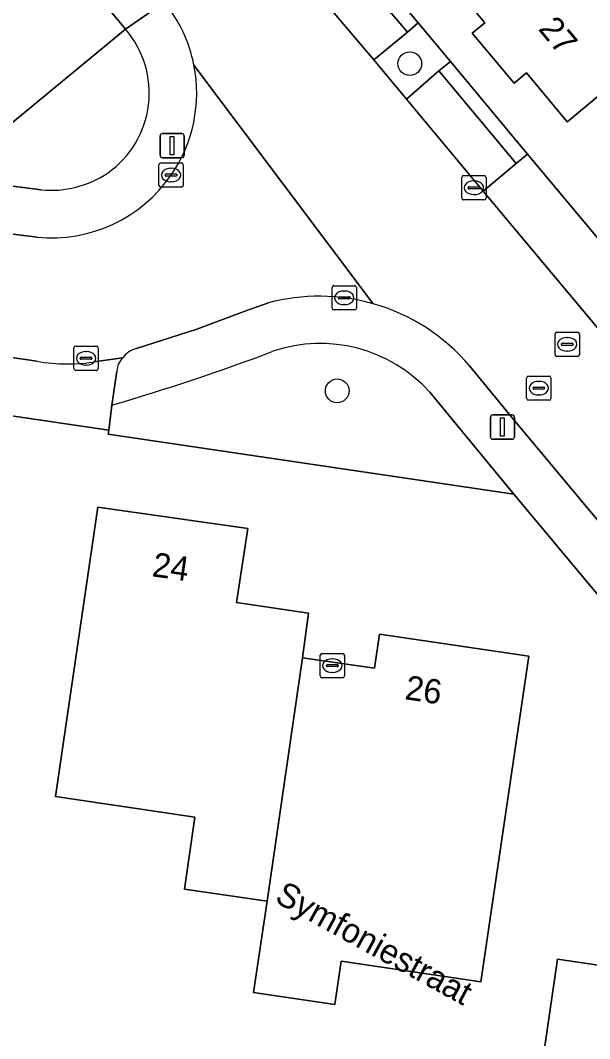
# Model space of a CAD drawing. Extents: x 164148 to 165261, y 382513 to 383432.
# Drawn here: x 164753.29 to 164776.74, y 383011.96 to 383053.88 of the extents above; entities that cross this region are included whole.
import ezdxf

# ---------------------------------------------------------------- set-up
doc = ezdxf.new("R2010")
doc.units = 0
for name, color, linetype in [('IMGEO_Boom', 7, 'Continuous'), ('IMGEO_Erf', 7, 'Continuous'), ('IMGEO_Groenvoorziening', 7, 'Continuous'), ('IMGEO_Kolk', 7, 'Continuous'), ('IMGEO_Lichtmast', 7, 'Continuous'), ('IMGEO_Openbare_ruimte_label', 7, 'Continuous'), ('IMGEO_Pand', 7, 'Continuous'), ('IMGEO_Pand_nummerreeks', 7, 'Continuous'), ('IMGEO_Parkeervlak_open', 7, 'Continuous'), ('IMGEO_Rijbaan_lokaal_open', 7, 'Continuous'), ('IMGEO_Rioolput', 7, 'Continuous'), ('IMGEO_Voetpad_open', 7, 'Continuous')]:
    doc.layers.add(name, color=color, linetype=linetype)

msp = doc.modelspace()

# ---------------------------------------------------------------- linework, layer by layer
at = {"layer": 'IMGEO_Boom'}
for centre in [(164769.334, 383052.103), (164766.345, 383038.63)]:
    msp.add_circle(centre, 0.489, dxfattribs=at)
at = {"layer": 'IMGEO_Erf'}
for points in [[(164685.42, 383135.126), (164682.705, 383117.517), (164682.279, 383114.453), (164685.334, 383113.998), (164688.257, 383113.615), (164687.868, 383110.687), (164684.941, 383111.045), (164681.864, 383111.47), (164680.372, 383101.254), (164679.477, 383095.307), (164679.334, 383094.335), (164679.22, 383092.548), (164677.944, 383082.474), (164677.674, 383082.494), (164677.503, 383081.521), (164676.599, 383075.668), (164674.064, 383058.631), (164743.462, 383048.39), (164750.216, 383047.411), (164757.629, 383053.516), (164711.831, 383108.452)], [(164766.59, 383057.489), (164769.673, 383053.79), (164771.005, 383052.196), (164774.189, 383048.376), (164779.454, 383042.072), (164782.539, 383038.402), (164783.857, 383036.783), (164787.032, 383033.002), (164792.262, 383026.731), (164795.373, 383023.024), (164796.68, 383021.442)]]:
    msp.add_lwpolyline(points, dxfattribs=at)
for points in [[(164774.713, 383068.268), (164780.486, 383061.369), (164786.258, 383054.47), (164781.652, 383050.629), (164779.717, 383052.949), (164775.871, 383049.742), (164775.823, 383049.702), (164774.139, 383051.722), (164773.628, 383051.296), (164771.905, 383053.356), (164772.419, 383053.785), (164772.009, 383054.277), (164768.168, 383058.885), (164772.051, 383062.122), (164770.12, 383064.439)], [(164773.625, 383034.37), (164756.914, 383036.848), (164756.945, 383037.007), (164750.961, 383037.884), (164745.467, 383038.7), (164743.325, 383039.011), (164732.535, 383040.594), (164726.832, 383041.442), (164721.322, 383042.249), (164719.176, 383042.567), (164708.591, 383044.131), (164702.568, 383045.027), (164697.666, 383045.734), (164696.644, 383045.892), (164694.5, 383046.223), (164676.627, 383048.817), (164672.72, 383049.384), (164670.369, 383036.742), (164669.457, 383030.808), (164668.043, 383018.43), (164792.926, 382999.883), (164794.329, 383009.577), (164793.988, 383009.985)], [(164764.912, 383027.637), (164767.886, 383027.211), (164768.092, 383028.613), (164774.238, 383027.703), (164772.256, 383014.304), (164766.51, 383015.154), (164766.246, 383013.368), (164762.899, 383013.863), (164763.455, 383017.62), (164760.052, 383018.118), (164760.487, 383021.077), (164754.735, 383021.923), (164756.488, 383033.841), (164762.657, 383032.956), (164762.202, 383029.922), (164765.166, 383029.471)], [(164784.293, 383018.222), (164784.196, 383017.562), (164785.081, 383017.432), (164783.318, 383005.501), (164774.198, 383006.849), (164775.415, 383015.23), (164778.393, 383014.789), (164778.918, 383018.342), (164781.485, 383017.963), (164781.583, 383018.623)]]:
    msp.add_lwpolyline(points, close=True, dxfattribs=at)
at = {"layer": 'IMGEO_Groenvoorziening'}
msp.add_lwpolyline([(164769.673, 383053.79), (164769.236, 383053.402), (164767.857, 383052.253), (164769.192, 383050.647), (164770.53, 383051.801), (164771.005, 383052.196)], close=True, dxfattribs=at)
for points in [[(164757.629, 383053.516), (164750.216, 383047.411), (164754.15, 383046.907)], [(164757.064, 383038.043), (164756.945, 383037.007), (164756.914, 383036.848), (164773.625, 383034.37), (164770.154, 383038.576)]]:
    msp.add_lwpolyline(points, dxfattribs=at)
for centre, radius, start, end in [((164754.581, 383050.892), 4.022, 305.3329, 40.7253), ((164754.557, 383051.062), 4.175, 264.3994, 304.2494), ((164731.985, 383124.094), 89.631, 286.24859, 290.71977), ((164765.647, 383034.515), 6.067, 42.0159, 108.7539)]:
    msp.add_arc(centre, radius, start, end, dxfattribs=at)
at = {"layer": 'IMGEO_Kolk'}
for p, q in [((164759.004, 383047.091), (164759.004, 383047.943)), ((164759.079, 383048.017), (164759.931, 383048.017)), ((164760.005, 383047.943), (164760.005, 383047.091)), ((164759.263, 383047.511), (164759.263, 383047.523)), ((164759.701, 383047.474), (164759.303, 383047.474)), ((164759.306, 383047.56), (164759.704, 383047.56)), ((164759.492, 383047.797), (164759.517, 383047.797)), ((164759.747, 383047.523), (164759.747, 383047.511)), ((164771.474, 383046.566), (164771.474, 383047.418)), ((164771.549, 383047.492), (164772.401, 383047.492)), ((164772.475, 383047.418), (164772.475, 383046.566)), ((164759.931, 383047.017), (164759.079, 383047.017)), ((164759.515, 383047.237), (164759.49, 383047.237)), ((164771.733, 383046.986), (164771.733, 383046.998)), ((164771.776, 383047.035), (164772.174, 383047.035)), ((164771.962, 383047.272), (164771.987, 383047.272)), ((164772.217, 383046.998), (164772.217, 383046.986)), ((164772.171, 383046.949), (164771.773, 383046.949)), ((164771.985, 383046.712), (164771.96, 383046.712)), ((164772.401, 383046.492), (164771.549, 383046.492)), ((164766.133, 383042.035), (164766.133, 383042.887)), ((164766.208, 383042.961), (164767.06, 383042.961)), ((164767.134, 383042.887), (164767.134, 383042.035)), ((164766.392, 383042.455), (164766.392, 383042.467)), ((164766.83, 383042.418), (164766.432, 383042.418)), ((164766.435, 383042.504), (164766.833, 383042.504)), ((164766.621, 383042.741), (164766.646, 383042.741)), ((164766.876, 383042.467), (164766.876, 383042.455)), ((164767.06, 383041.961), (164766.208, 383041.961)), ((164766.644, 383042.181), (164766.619, 383042.181)), ((164755.501, 383039.547), (164755.501, 383040.399)), ((164755.576, 383040.473), (164756.428, 383040.473)), ((164756.502, 383040.399), (164756.502, 383039.547)), ((164755.76, 383039.967), (164755.76, 383039.979)), ((164756.198, 383039.93), (164755.8, 383039.93)), ((164755.803, 383040.016), (164756.201, 383040.016)), ((164755.989, 383040.253), (164756.014, 383040.253)), ((164756.244, 383039.979), (164756.244, 383039.967)), ((164756.428, 383039.473), (164755.576, 383039.473)), ((164756.012, 383039.693), (164755.987, 383039.693))]:
    msp.add_line(p, q, dxfattribs=at)
for points in [[(164759.004, 383047.091), (164759.004, 383047.943)], [(164759.079, 383048.017), (164759.931, 383048.017)], [(164760.005, 383047.943), (164760.005, 383047.091)], [(164771.474, 383046.566), (164771.474, 383047.418)], [(164771.549, 383047.492), (164772.401, 383047.492)], [(164772.475, 383047.418), (164772.475, 383046.566)], [(164759.931, 383047.017), (164759.079, 383047.017)], [(164772.401, 383046.492), (164771.549, 383046.492)], [(164766.133, 383042.035), (164766.133, 383042.887)], [(164766.208, 383042.961), (164767.06, 383042.961)], [(164767.134, 383042.887), (164767.134, 383042.035)], [(164767.06, 383041.961), (164766.208, 383041.961)], [(164755.501, 383039.547), (164755.501, 383040.399)], [(164755.576, 383040.473), (164756.428, 383040.473)], [(164756.502, 383040.399), (164756.502, 383039.547)], [(164756.428, 383039.473), (164755.576, 383039.473)]]:
    msp.add_lwpolyline(points, dxfattribs=at)
for centre, radius, start, end in [((164759.081, 383047.941), 0.0765, 91.552, 178.448), ((164759.081, 383047.941), 0.0765, 91.552, 178.448), ((164759.929, 383047.941), 0.0765, 1.552, 88.448), ((164759.929, 383047.941), 0.0765, 1.552, 88.448), ((164759.303, 383047.52), 0.0403, 85.8775, 175.7526), ((164759.3, 383047.51), 0.0366, 178.938, 274.7102), ((164759.704, 383047.517), 0.043, 264.8664, 352.4533), ((164759.708, 383047.522), 0.0386, 1.7309, 96.639), ((164771.551, 383047.416), 0.0765, 91.552, 178.448), ((164771.551, 383047.416), 0.0765, 91.552, 178.448), ((164772.399, 383047.416), 0.0765, 1.552, 88.448), ((164772.399, 383047.416), 0.0765, 1.552, 88.448), ((164759.081, 383047.093), 0.0765, 181.552, 268.448), ((164759.081, 383047.093), 0.0765, 181.552, 268.448), ((164759.929, 383047.093), 0.0765, 271.552, 358.448), ((164759.929, 383047.093), 0.0765, 271.552, 358.448), ((164771.773, 383046.995), 0.0403, 85.8775, 175.7526), ((164771.77, 383046.985), 0.0366, 178.938, 274.7102), ((164772.174, 383046.992), 0.043, 264.8664, 352.4533), ((164772.178, 383046.997), 0.0386, 1.7309, 96.639), ((164771.551, 383046.568), 0.0765, 181.552, 268.448), ((164771.551, 383046.568), 0.0765, 181.552, 268.448), ((164772.399, 383046.568), 0.0765, 271.552, 358.448), ((164772.399, 383046.568), 0.0765, 271.552, 358.448), ((164766.21, 383042.885), 0.0765, 91.552, 178.448), ((164766.21, 383042.885), 0.0765, 91.552, 178.448), ((164767.058, 383042.885), 0.0765, 1.552, 88.448), ((164767.058, 383042.885), 0.0765, 1.552, 88.448), ((164766.432, 383042.464), 0.0403, 85.8775, 175.7526), ((164766.429, 383042.454), 0.0366, 178.938, 274.7102), ((164766.833, 383042.461), 0.043, 264.8664, 352.4533), ((164766.837, 383042.466), 0.0386, 1.7309, 96.639), ((164766.21, 383042.037), 0.0765, 181.552, 268.448), ((164766.21, 383042.037), 0.0765, 181.552, 268.448), ((164767.058, 383042.037), 0.0765, 271.552, 358.448), ((164767.058, 383042.037), 0.0765, 271.552, 358.448), ((164755.578, 383040.397), 0.0765, 91.552, 178.448), ((164755.578, 383040.397), 0.0765, 91.552, 178.448), ((164756.426, 383040.397), 0.0765, 1.552, 88.448), ((164756.426, 383040.397), 0.0765, 1.552, 88.448), ((164755.8, 383039.976), 0.0403, 85.8775, 175.7526), ((164755.797, 383039.966), 0.0366, 178.938, 274.7102), ((164756.201, 383039.973), 0.043, 264.8664, 352.4533), ((164756.205, 383039.978), 0.0386, 1.7309, 96.639), ((164755.578, 383039.549), 0.0765, 181.552, 268.448), ((164755.578, 383039.549), 0.0765, 181.552, 268.448), ((164756.426, 383039.549), 0.0765, 271.552, 358.448), ((164756.426, 383039.549), 0.0765, 271.552, 358.448)]:
    msp.add_arc(centre, radius, start, end, dxfattribs=at)
for centre, major_axis, ratio, start_param, end_param in [((164759.491, 383047.517), (-0.387, 0.002), 0.722429, 4.712389, 7.853982), ((164759.516, 383047.517), (-0.39, 0.002), 0.717154, 1.570796, 4.712389), ((164771.961, 383046.992), (-0.387, 0.002), 0.722429, 4.712389, 7.853982), ((164771.986, 383046.992), (-0.39, 0.002), 0.717154, 1.570796, 4.712389), ((164766.62, 383042.461), (-0.387, 0.002), 0.722429, 4.712389, 7.853982), ((164766.645, 383042.461), (-0.39, 0.002), 0.717154, 1.570796, 4.712389), ((164755.988, 383039.973), (-0.387, 0.002), 0.722429, 4.712389, 7.853982), ((164756.013, 383039.973), (-0.39, 0.002), 0.717154, 1.570796, 4.712389)]:
    msp.add_ellipse(centre, major_axis=major_axis, ratio=ratio, start_param=start_param, end_param=end_param, dxfattribs=at)
at = {"layer": 'IMGEO_Lichtmast'}
for p, q in [((164759.05, 383048.327), (164759.05, 383049.127)), ((164759.05, 383049.127), (164759.05, 383048.327)), ((164759.15, 383049.227), (164759.94, 383049.227)), ((164759.94, 383049.227), (164759.15, 383049.227)), ((164760.04, 383049.127), (164760.04, 383048.327)), ((164760.04, 383048.327), (164760.04, 383049.127)), ((164759.94, 383048.227), (164759.15, 383048.227)), ((164759.15, 383048.227), (164759.94, 383048.227)), ((164772.657, 383036.738), (164772.657, 383037.538)), ((164772.657, 383037.538), (164772.657, 383036.738)), ((164772.757, 383037.638), (164773.547, 383037.638)), ((164773.547, 383037.638), (164772.757, 383037.638)), ((164773.647, 383037.538), (164773.647, 383036.738)), ((164773.647, 383036.738), (164773.647, 383037.538)), ((164773.547, 383036.638), (164772.757, 383036.638)), ((164772.757, 383036.638), (164773.547, 383036.638))]:
    msp.add_line(p, q, dxfattribs=at)
for points in [[(164759.47, 383049.102), (164759.62, 383049.102), (164759.62, 383048.352), (164759.47, 383048.352), (164759.47, 383049.102)], [(164773.077, 383037.513), (164773.227, 383037.513), (164773.227, 383036.763), (164773.077, 383036.763), (164773.077, 383037.513)]]:
    msp.add_lwpolyline(points, dxfattribs=at)
for centre, start, end in [((164759.15, 383049.127), 90, 180), ((164759.15, 383049.127), 90, 180), ((164759.94, 383049.127), 0, 90), ((164759.94, 383049.127), 360, 90), ((164759.15, 383048.327), 180, 270), ((164759.15, 383048.327), 180, 270), ((164759.94, 383048.327), 270, 0), ((164759.94, 383048.327), 270, 0), ((164772.757, 383037.538), 90, 180), ((164772.757, 383037.538), 90, 180), ((164773.547, 383037.538), 0, 90), ((164773.547, 383037.538), 360, 90), ((164772.757, 383036.738), 180, 270), ((164772.757, 383036.738), 180, 270), ((164773.547, 383036.738), 270, 0), ((164773.547, 383036.738), 270, 0)]:
    msp.add_arc(centre, 0.1, start, end, dxfattribs=at)
at = {"layer": 'IMGEO_Pand'}
for points in [[(164780.486, 383061.369), (164772.009, 383054.277), (164772.419, 383053.785), (164771.905, 383053.356), (164773.628, 383051.296), (164774.139, 383051.722), (164775.823, 383049.702), (164775.871, 383049.742), (164779.717, 383052.949), (164781.652, 383050.629), (164786.258, 383054.47)], [(164764.912, 383027.637), (164765.166, 383029.471), (164762.202, 383029.922), (164762.657, 383032.956), (164756.488, 383033.841), (164754.735, 383021.923), (164760.487, 383021.077), (164760.052, 383018.118), (164763.455, 383017.62)], [(164768.092, 383028.613), (164767.886, 383027.211), (164764.912, 383027.637), (164763.455, 383017.62), (164762.899, 383013.863), (164766.246, 383013.368), (164766.51, 383015.154), (164772.256, 383014.304), (164774.238, 383027.703)], [(164785.081, 383017.432), (164784.196, 383017.562), (164784.293, 383018.222), (164781.583, 383018.623), (164781.485, 383017.963), (164778.918, 383018.342), (164778.393, 383014.789), (164775.415, 383015.23), (164774.198, 383006.849), (164783.318, 383005.501)]]:
    msp.add_lwpolyline(points, close=True, dxfattribs=at)
at = {"layer": 'IMGEO_Parkeervlak_open'}
for points in [[(164766.111, 383057.083), (164764.743, 383055.943), (164767.857, 383052.253), (164769.236, 383053.402)], [(164770.53, 383051.801), (164769.192, 383050.647), (164772.36, 383046.857), (164773.722, 383047.994)]]:
    msp.add_lwpolyline(points, close=True, dxfattribs=at)
at = {"layer": 'IMGEO_Rijbaan_lokaal_open'}
for points in [[(164814.316, 382986.078), (164824.191, 382984.713), (164822.339, 382987.011), (164822.315, 382987.027), (164817.568, 382992.747), (164814.483, 382996.412), (164810.702, 383000.916), (164807.691, 383004.534), (164806.408, 383006.093), (164803.165, 383009.943), (164798.018, 383016.107), (164794.843, 383019.914), (164793.463, 383021.56), (164790.41, 383025.204), (164785.193, 383031.48), (164782.046, 383035.254), (164780.707, 383036.845), (164777.624, 383040.546), (164772.36, 383046.857), (164769.192, 383050.647), (164767.857, 383052.253), (164764.743, 383055.943), (164759.595, 383062.145)], [(164767.829, 383042.216), (164760.445, 383052.045)], [(164760.445, 383052.045), (164767.829, 383042.216)], [(164676.537, 383051.56), (164678.434, 383050.981), (164694.856, 383048.566), (164696.992, 383048.254), (164702.925, 383047.374), (164708.937, 383046.498), (164719.525, 383044.915), (164721.668, 383044.591), (164727.191, 383043.797), (164732.888, 383042.965), (164743.671, 383041.354), (164745.824, 383041.051), (164751.336, 383040.234), (164753.976, 383039.849)], [(164753.985, 383044.958), (164749.891, 383045.466), (164743.727, 383046.37), (164723.716, 383049.326)], [(164758.078, 383040.379), (164760.568, 383041.168), (164762.583, 383041.927), (164763.51, 383042.252)], [(164756.435, 383039.836), (164757.508, 383039.995)], [(164771.8, 383039.66), (164773.622, 383037.443), (164782.029, 383027.366), (164793.721, 383013.372), (164807.417, 382996.914), (164810.146, 382993.692), (164812.326, 382991.078)]]:
    msp.add_lwpolyline(points, dxfattribs=at)
for centre, radius, start, end in [((164754.627, 383050.887), 5.932, 11.2559, 39.1698), ((164754.626, 383050.891), 5.932, 325.3304, 11.2138), ((164754.578, 383050.911), 5.983, 264.3074, 325.4363), ((164765.604, 383034.401), 8.125, 74.1087, 104.9362), ((164765.606, 383034.4), 8.126, 40.3397, 74.1242), ((164758.328, 383039.393), 1.017, 104.2286, 143.7065), ((164755.243, 383046.997), 7.259, 259.946, 279.4482)]:
    msp.add_arc(centre, radius, start, end, dxfattribs=at)
at = {"layer": 'IMGEO_Rioolput'}
for p, q in [((164775.317, 383040.12), (164775.317, 383040.972)), ((164775.392, 383041.046), (164776.244, 383041.046)), ((164775.805, 383040.826), (164775.83, 383040.826)), ((164776.318, 383040.972), (164776.318, 383040.12)), ((164775.576, 383040.54), (164775.576, 383040.552)), ((164776.014, 383040.503), (164775.616, 383040.503)), ((164775.619, 383040.589), (164776.017, 383040.589)), ((164775.828, 383040.266), (164775.803, 383040.266)), ((164776.06, 383040.552), (164776.06, 383040.54)), ((164776.244, 383040.046), (164775.392, 383040.046)), ((164774.148, 383038.315), (164774.148, 383039.167)), ((164774.223, 383039.241), (164775.075, 383039.241)), ((164774.636, 383039.021), (164774.661, 383039.021)), ((164775.149, 383039.167), (164775.149, 383038.315)), ((164774.407, 383038.735), (164774.407, 383038.747)), ((164774.845, 383038.698), (164774.447, 383038.698)), ((164774.45, 383038.784), (164774.848, 383038.784)), ((164774.891, 383038.747), (164774.891, 383038.735)), ((164775.075, 383038.241), (164774.223, 383038.241)), ((164774.659, 383038.461), (164774.634, 383038.461)), ((164765.643, 383026.891), (164765.643, 383027.743)), ((164765.718, 383027.817), (164766.57, 383027.817)), ((164766.644, 383027.743), (164766.644, 383026.891)), ((164765.902, 383027.311), (164765.902, 383027.323)), ((164766.34, 383027.274), (164765.942, 383027.274)), ((164765.945, 383027.36), (164766.343, 383027.36)), ((164766.131, 383027.597), (164766.156, 383027.597)), ((164766.386, 383027.323), (164766.386, 383027.311)), ((164766.154, 383027.037), (164766.129, 383027.037)), ((164766.57, 383026.817), (164765.718, 383026.817))]:
    msp.add_line(p, q, dxfattribs=at)
for points in [[(164775.317, 383040.12), (164775.317, 383040.972)], [(164775.392, 383041.046), (164776.244, 383041.046)], [(164776.318, 383040.972), (164776.318, 383040.12)], [(164776.244, 383040.046), (164775.392, 383040.046)], [(164774.148, 383038.315), (164774.148, 383039.167)], [(164774.223, 383039.241), (164775.075, 383039.241)], [(164775.149, 383039.167), (164775.149, 383038.315)], [(164775.075, 383038.241), (164774.223, 383038.241)], [(164765.643, 383026.891), (164765.643, 383027.743)], [(164765.718, 383027.817), (164766.57, 383027.817)], [(164766.644, 383027.743), (164766.644, 383026.891)], [(164766.57, 383026.817), (164765.718, 383026.817)]]:
    msp.add_lwpolyline(points, dxfattribs=at)
for centre, radius, start, end in [((164775.394, 383040.97), 0.0765, 91.552, 178.448), ((164775.394, 383040.97), 0.0765, 91.552, 178.448), ((164776.242, 383040.97), 0.0765, 1.552, 88.448), ((164776.242, 383040.97), 0.0765, 1.552, 88.448), ((164775.616, 383040.549), 0.0403, 85.8775, 175.7526), ((164775.613, 383040.539), 0.0366, 178.938, 274.7102), ((164776.017, 383040.546), 0.043, 264.8664, 352.4533), ((164776.021, 383040.551), 0.0386, 1.7309, 96.639), ((164775.394, 383040.122), 0.0765, 181.552, 268.448), ((164775.394, 383040.122), 0.0765, 181.552, 268.448), ((164776.242, 383040.122), 0.0765, 271.552, 358.448), ((164776.242, 383040.122), 0.0765, 271.552, 358.448), ((164774.225, 383039.165), 0.0765, 91.552, 178.448), ((164774.225, 383039.165), 0.0765, 91.552, 178.448), ((164775.073, 383039.165), 0.0765, 1.552, 88.448), ((164775.073, 383039.165), 0.0765, 1.552, 88.448), ((164774.447, 383038.744), 0.0403, 85.8775, 175.7526), ((164774.444, 383038.734), 0.0366, 178.938, 274.7102), ((164774.848, 383038.741), 0.043, 264.8664, 352.4533), ((164774.852, 383038.746), 0.0386, 1.7309, 96.639), ((164774.225, 383038.317), 0.0765, 181.552, 268.448), ((164774.225, 383038.317), 0.0765, 181.552, 268.448), ((164775.073, 383038.317), 0.0765, 271.552, 358.448), ((164775.073, 383038.317), 0.0765, 271.552, 358.448), ((164765.72, 383027.741), 0.0765, 91.552, 178.448), ((164765.72, 383027.741), 0.0765, 91.552, 178.448), ((164766.568, 383027.741), 0.0765, 1.552, 88.448), ((164766.568, 383027.741), 0.0765, 1.552, 88.448), ((164765.942, 383027.32), 0.0403, 85.8775, 175.7526), ((164765.939, 383027.31), 0.0366, 178.938, 274.7102), ((164766.343, 383027.317), 0.043, 264.8664, 352.4533), ((164766.347, 383027.322), 0.0386, 1.7309, 96.639), ((164765.72, 383026.893), 0.0765, 181.552, 268.448), ((164765.72, 383026.893), 0.0765, 181.552, 268.448), ((164766.568, 383026.893), 0.0765, 271.552, 358.448), ((164766.568, 383026.893), 0.0765, 271.552, 358.448)]:
    msp.add_arc(centre, radius, start, end, dxfattribs=at)
for centre, major_axis, ratio, start_param, end_param in [((164775.804, 383040.546), (-0.387, 0.002), 0.722429, 4.712389, 7.853982), ((164775.829, 383040.546), (-0.39, 0.002), 0.717154, 1.570796, 4.712389), ((164774.635, 383038.741), (-0.387, 0.002), 0.722429, 4.712389, 7.853982), ((164774.66, 383038.741), (-0.39, 0.002), 0.717154, 1.570796, 4.712389), ((164766.13, 383027.317), (-0.387, 0.002), 0.722429, 4.712389, 7.853982), ((164766.155, 383027.317), (-0.39, 0.002), 0.717154, 1.570796, 4.712389)]:
    msp.add_ellipse(centre, major_axis=major_axis, ratio=ratio, start_param=start_param, end_param=end_param, dxfattribs=at)
at = {"layer": 'IMGEO_Voetpad_open'}
for points in [[(164693.959, 383129.801), (164704.347, 383117.418), (164711.831, 383108.452), (164757.629, 383053.516), (164759.226, 383054.634), (164755.138, 383059.563), (164742.049, 383075.319), (164733.429, 383085.658)], [(164754.15, 383046.907), (164750.216, 383047.411), (164743.462, 383048.39), (164674.064, 383058.631), (164673.685, 383058.687), (164672.813, 383058.815)], [(164673.104, 383056.788), (164673.758, 383056.679), (164684.631, 383055.087), (164702.697, 383052.429), (164723.716, 383049.326), (164743.727, 383046.37), (164749.891, 383045.466), (164753.985, 383044.958)], [(164759.226, 383054.634), (164757.629, 383053.516)], [(164763.51, 383042.252), (164762.583, 383041.927), (164760.568, 383041.168), (164758.078, 383040.379)], [(164753.976, 383039.849), (164751.336, 383040.234), (164751.055, 383038.466), (164750.961, 383037.884), (164756.945, 383037.007), (164757.064, 383038.043), (164757.269, 383039.441)], [(164757.508, 383039.995), (164756.435, 383039.836)], [(164757.269, 383039.441), (164757.064, 383038.043)], [(164793.721, 383013.372), (164782.029, 383027.366), (164773.622, 383037.443), (164771.8, 383039.66)], [(164770.154, 383038.576), (164773.625, 383034.37), (164793.988, 383009.985), (164794.329, 383009.577), (164807.059, 382994.322), (164810.811, 382989.816)]]:
    msp.add_lwpolyline(points, dxfattribs=at)
for points in [[(164766.59, 383057.489), (164766.111, 383057.083), (164769.236, 383053.402), (164769.673, 383053.79)], [(164771.005, 383052.196), (164770.53, 383051.801), (164773.722, 383047.994), (164774.189, 383048.376)], [(164774.189, 383048.376), (164773.722, 383047.994), (164772.36, 383046.857), (164777.624, 383040.546), (164778.997, 383041.695), (164779.454, 383042.072)]]:
    msp.add_lwpolyline(points, close=True, dxfattribs=at)
for centre, radius, start, end in [((164754.627, 383050.887), 5.932, 11.2559, 39.1698), ((164754.581, 383050.892), 4.022, 305.3329, 40.7253), ((164754.626, 383050.891), 5.932, 325.3304, 11.2138), ((164754.578, 383050.911), 5.983, 264.3074, 325.4363), ((164754.557, 383051.062), 4.175, 264.3994, 304.2494), ((164765.604, 383034.401), 8.125, 74.1087, 104.9362), ((164765.606, 383034.4), 8.126, 40.3397, 74.1242), ((164731.985, 383124.094), 89.631, 286.24859, 290.71977), ((164758.328, 383039.393), 1.017, 104.2286, 143.7065), ((164765.647, 383034.515), 6.067, 42.0159, 108.7539), ((164755.243, 383046.997), 7.259, 259.946, 279.4482), ((164758.144, 383039.392), 0.876, 136.5202, 176.8083), ((164758.144, 383039.392), 0.876, 136.5202, 176.8083)]:
    msp.add_arc(centre, radius, start, end, dxfattribs=at)

# ---------------------------------------------------------------- texts
at = {"layer": 'IMGEO_Openbare_ruimte_label'}
msp.add_text('Symfoniestraat', height=1, rotation=331.1792, dxfattribs=at).set_placement((164763.725, 383017.61))
at = {"layer": 'IMGEO_Pand_nummerreeks'}
for s, rotation, p in [('27', 309.8146, (164774.591, 383053.522)), ('24', 351.8354, (164758.687, 383030.999)), ('26', 351.5775, (164769.099, 383025.936))]:
    msp.add_text(s, height=1, rotation=rotation, dxfattribs=at).set_placement(p)

doc.saveas('drawing.dxf')
